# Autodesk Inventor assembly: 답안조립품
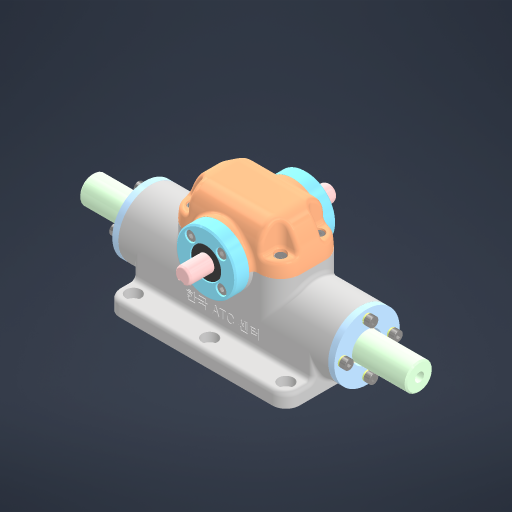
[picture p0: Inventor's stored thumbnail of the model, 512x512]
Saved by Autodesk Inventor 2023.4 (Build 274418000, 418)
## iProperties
Created: 2024-06
Part Number: 답안조립품
Document SubType Name: Assembly
Designer: Edu03
Author: Edu03
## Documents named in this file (13)
- C:\Users\Edu03\Desktop\740604V1004\답안조립품.iam
- C:\Users\Edu03\Desktop\740604V1004\오일레스 부시.ipt
- C:\Users\Edu03\Desktop\740604V1004\오일실 12 22 7.ipt
- C:\Users\Edu03\Desktop\740604V1004\윗커버.ipt
- C:\Users\Edu03\Desktop\740604V1004\육각 소켓 머리 볼트 M4x10.ipt
- C:\Users\Edu03\Desktop\740604V1004\칼라.ipt
- C:\Users\Edu03\Desktop\740604V1004\피니언.ipt
- C:\Users\Edu03\Desktop\740604V1004\깊은 홈 볼 베어링 6901.ipt
- C:\Users\Edu03\Desktop\740604V1004\랙.ipt
- C:\Users\Edu03\Desktop\740604V1004\베어링 커버.ipt
- C:\Users\Edu03\Desktop\740604V1004\본체.ipt
- C:\Users\Edu03\Desktop\740604V1004\부시 커버.ipt
- C:\Users\Edu03\Desktop\740604V1004\스프링 와셔 M4.ipt
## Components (1 placed, 1 different names)
1. 피니언:1
